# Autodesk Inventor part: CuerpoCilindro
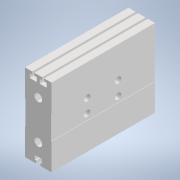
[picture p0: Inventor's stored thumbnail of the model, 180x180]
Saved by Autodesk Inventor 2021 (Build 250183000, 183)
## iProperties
Created: 2021-02
Part Number: CuerpoCilindro
Material: Genérico
Document SubType Name: Modeling
Designer: ATOUZA
Density: 1 g/cm^3
Appearance: Valor por defecto
Author: ATOUZA
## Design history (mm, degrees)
sketch "Boceto1"
  geometry: L1 (-17.125, -50.2)-(17.125, 50.2); L2 (17.125, -50.2)-(-17.125, 50.2); L3 (-2.8, -50.2)-(-2.8, -46.8); L4 (-2.8, -46.8)-(-4.5, -46.8); L5 (-4.5, -46.8)-(-4.5, -41.4); L6 (-4.5, -41.4)-(0, -41.4); L7 (0, -50.2)-(0, 50.2); L8 (2.8, -50.2)-(2.8, -46.8); L9 (2.8, -46.8)-(4.5, -46.8); L10 (4.5, -46.8)-(4.5, -41.4); L11 (4.5, -41.4)-(0, -41.4); L12 (-17.125, -50.2)-(-2.8, -50.2); L13 (2.8, -50.2)-(17.125, -50.2); L14 (-7.8, 50.2)-(-7.8, 46.8); L15 (-7.8, 46.8)-(-10.9, 46.8); L16 (-10.9, 46.8)-(-10.9, 41.4); L17 (-10.9, 41.4)-(-1.9, 41.4); L18 (-1.9, 41.4)-(-1.9, 46.8); L19 (-1.9, 46.8)-(-5, 46.8); L20 (-5, 46.8)-(-5, 50.2); L21 (10.9, 46.8)-(10.9, 41.4); L22 (10.9, 41.4)-(1.9, 41.4); L23 (1.9, 41.4)-(1.9, 46.8); L24 (1.9, 46.8)-(5, 46.8); L25 (5, 46.8)-(5, 50.2); L26 (7.8, 50.2)-(7.8, 46.8); L27 (7.8, 46.8)-(10.9, 46.8); L28 (-7.8, 50.2)-(-17.125, 50.2); L29 (17.125, 50.2)-(7.8, 50.2); L30 (5, 50.2)-(-5, 50.2); L31 (-17.125, 0)-(17.125, 0); L32 (-17.125, -15.5)-(-16.625, -15.5); L33 (-16.625, -15.5)-(-16.625, 15.5); L34 (-16.625, 15.5)-(-17.125, 15.5); L35 (-17.125, 50.2)-(-17.125, 15.5); L36 (-17.125, -15.5)-(-17.125, -50.2); L37 (16.625, -15.5)-(16.625, 15.5); L38 (17.125, -15.5)-(16.625, -15.5); L39 (16.625, 15.5)-(17.125, 15.5); L40 (17.125, -50.2)-(17.125, -15.5); L41 (17.125, 15.5)-(17.125, 50.2); C1 r 5 at (0, -25); C2 r 5 at (0, 25); 1 further point
  constraints: 82 end point, 17 perpendicular, 17 symmetric about line, 10 parallel, 6 point on line, 3 horizontal, 3 midpoint, 3 vertical, 2 centre point, 1 other
  dimensions: "d0" = 34.25 distance of L2.end L1.end; "d1" = 100.4 distance of L1.end L2.start; "d2" = 2.8 distance between parallel lines of L3 L7; "d3" = 4.5 distance between parallel lines of L5 L7; "d5" = 5.4 distance between parallel lines of L6 L4; "d6" = 3.4 distance of L3.start L3.end; "d8" = 5.4 distance between parallel lines of L17 L15; "d9" = 9 distance of L16.end L17.end; "d10" = 2.8 distance between parallel lines of L14 L20; "d11" = 3.1 distance between parallel lines of L20 L18; "d12" = 5 distance between parallel lines of L7 L20; "d13" = 10 diameter of C1; "d14" = 25 distance of point (0, 0) C1.centre; "d15" = 31 distance between parallel lines of L32 L34; "d16" = 15.5 distance between parallel lines of L31 L34
extrude "Extrusión1" new body sketch "Boceto1" distance "d18" = 133.75; taper "d19" = 0 deg
sketch "Boceto2"
  geometry: L1 (0, 15.5)-(-133.75, 16.728); L2 (-133.75, 31)-(-133.75, 0) reference; L3 (0, -34.7)-(0, 0) reference; L4 (0, 0)-(0, 31) reference; L5 (0, 0)-(0, 31); C1 r 4 at (-47, 24.932); C2 r 4 at (-87, 24.932); C3 r 4 at (-87.158, 7.667); C4 r 4 at (-47.165, 6.933)
  constraints: 4 centre point, 4 end point, 2 symmetric about line, 1 collinear, 1 point on line, 2 other
  dimensions: "d20" = 8 diameter of C1; "d21" = 9 distance from line of L1 C1.centre; "d22" = 8 diameter of C2; "d23" = 40 distance of C1.centre C2.centre; "d24" = 47 distance from line of L4 C1.centre
extrude "Extrusión2" cut sketch "Boceto2" extent not by distance; stored distance "d25" = 0.5; taper "d26" = 0 deg
node "Sólido1"
other parameters: "d4" = 3.4, "d7" = 3.4, "d17" = 0.5
